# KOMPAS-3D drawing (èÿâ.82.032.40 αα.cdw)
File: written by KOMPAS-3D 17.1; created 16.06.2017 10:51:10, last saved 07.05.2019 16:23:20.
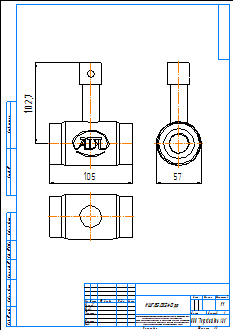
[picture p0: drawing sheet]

Sheet 1: A3, portrait

Title block, sheet 1: name: КШГ.82.032.40 рр; material: Внимание! Данный продукт является объектом авторского права ООО «Торговый Дом АДЛ». / Запрещается изменение, копирование, распространение / (в том числе путем копирования на другие сайты и ресурсы в Интернете) / или любое иное использование информации и объектов без предварительного / согласия правообладателя (ООО «Торговый Дом АДЛ»).; scale: 1:1; sheets: 1; organisation: ООО "Торговый дом АДЛ"; sheet format: A3; stored path: C:\Users\tra\Desktop\2д чертежи\Шаровые краны БИВАЛ\КШ_Бивал_серия_82_85\KOMPAS 2D\КШГ.82.032.40 рр.cdw

Views: Спереди 1, Проекционный вид 2, Проекционный вид 3
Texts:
  Klimkovich
  ADL
Dimensions and other numbers on the sheet: 105; 102,7; 57; 1:1; 1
